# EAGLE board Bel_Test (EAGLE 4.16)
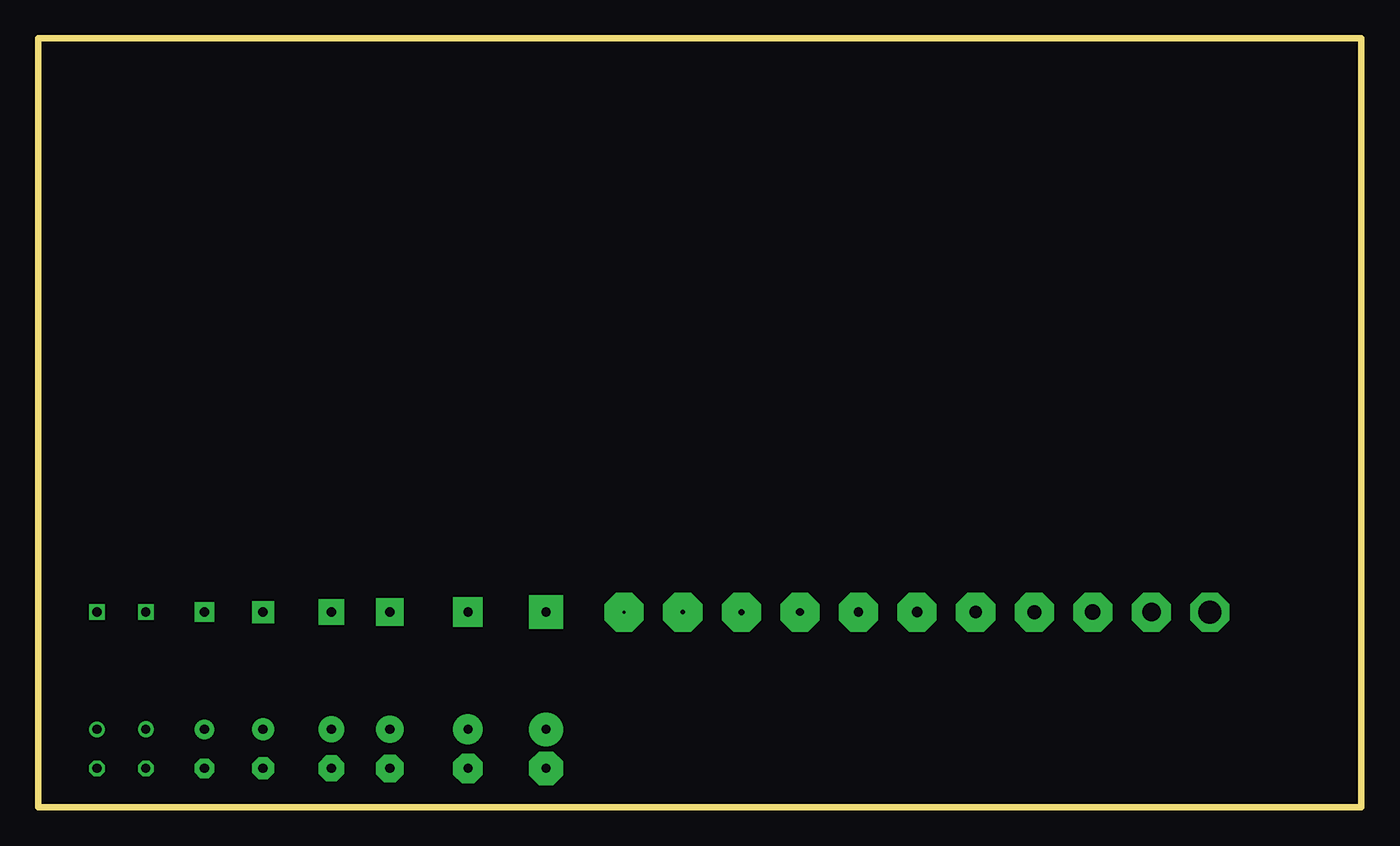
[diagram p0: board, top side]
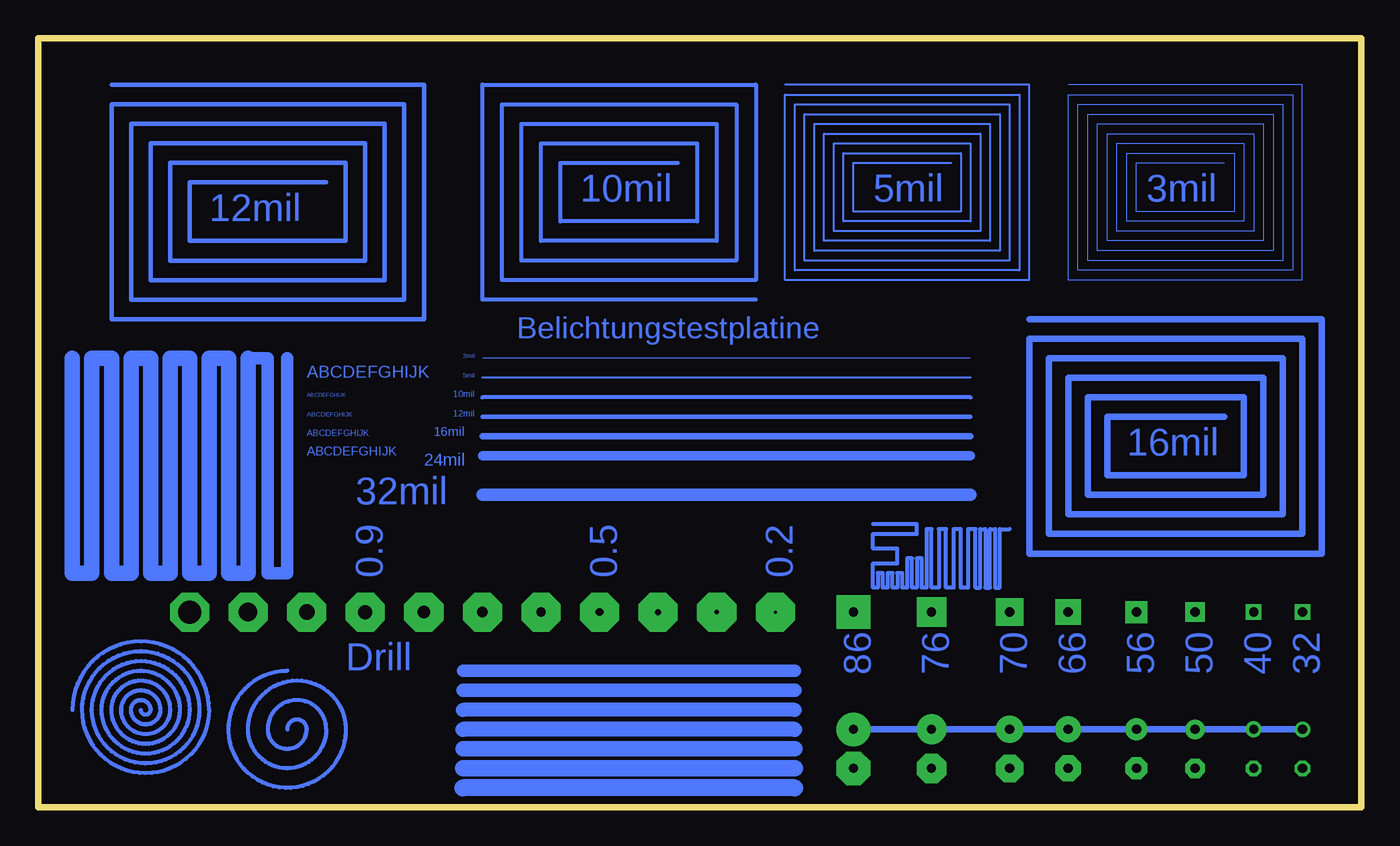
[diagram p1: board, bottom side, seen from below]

Size 86.03 x 50 mm. Coordinates in mm from the lower left corner, seen from the top.
Outline: 0,0 86.03,0 86.03,50 0,50 0,0
Copper layers (1*16): Top 0.035mm / dielectric 1.5mm / Bottom 0.035mm
Design rules "default": minimum track width 10mil, minimum drill 24mil, track to track 8mil, track to pad 8mil, pad to pad 8mil, via to via 8mil, smd to smd 8mil, copper to edge 40mil, drill to drill 8mil, minimum pad ring 10mil, minimum via ring 8mil, stop-mask expansion 4mil, vias tented up to drill 0mil, thermal gap 10mil

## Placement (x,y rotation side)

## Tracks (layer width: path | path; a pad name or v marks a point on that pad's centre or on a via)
S$1
  Bottom 0.254: 44.45,41.91 52.07,41.91 52.07,38.1 43.18,38.1 43.18,43.18 53.34,43.18 53.34,36.83 41.91,36.83 41.91,44.45 54.61,44.45 54.61,35.56 40.64,35.56 40.64,45.72 55.88,45.72 55.88,34.29 39.37,34.29 39.37,46.99 57.15,46.99 57.15,33.02 39.37,33.02
S$2
  Bottom 0.305: 67.31,40.64 76.2,40.64 76.2,36.83 66.04,36.83 66.04,41.91 77.47,41.91 77.47,35.56 64.77,35.56 64.77,43.18 78.74,43.18 78.74,34.29 63.5,34.29 63.5,44.45 80.01,44.45 80.01,33.02 62.23,33.02 62.23,45.72 81.28,45.72 81.28,31.75 60.96,31.75 60.96,46.99 81.28,46.99
S$3
  Bottom 0.127: 26.67,41.91 33.02,41.91 33.02,38.73 26.04,38.73 26.04,42.55 33.66,42.55 33.66,38.1 25.4,38.1 25.4,43.18 34.29,43.18 34.29,37.47 24.77,37.47 24.77,43.81 34.92,43.81 34.92,36.83 24.13,36.83 24.13,44.45 35.56,44.45 35.56,36.2 23.5,36.2 23.5,45.09 36.2,45.09 36.2,35.56 22.86,35.56 22.86,45.72 36.83,45.72 36.83,34.92 22.23,34.92 22.23,46.35 37.47,46.35 37.47,34.29 21.59,34.29 21.59,46.99 37.47,46.99
S$4
  Bottom 0.406: 8.89,25.4 16.51,25.4 16.51,21.59 7.62,21.59 7.62,26.67 17.78,26.67 17.78,20.32 6.35,20.32 6.35,27.94 19.05,27.94 19.05,19.05 5.08,19.05 5.08,29.21 20.32,29.21 20.32,17.78 3.81,17.78 3.81,30.48 21.59,30.48 21.59,16.51 2.54,16.51 2.54,31.75 21.59,31.75
S$5
  Bottom 0.076: 8.89,41.91 14.61,41.91 14.61,38.73 8.26,38.73 8.26,42.55 15.24,42.55 15.24,38.1 7.62,38.1 7.62,43.18 15.88,43.18 15.88,37.47 6.99,37.47 6.99,43.81 16.51,43.81 16.51,36.83 6.35,36.83 6.35,44.45 17.14,44.45 17.14,36.2 5.71,36.2 5.71,45.09 17.78,45.09 17.78,35.56 5.08,35.56 5.08,45.72 18.41,45.72 18.41,34.92 4.45,34.92 4.45,46.35 19.05,46.35 19.05,34.29 3.81,34.29 3.81,46.99 19.05,46.99
S$6
  Bottom 0.076: 25.4,29.21 57.15,29.21
S$7
  Bottom 0.127: 25.4,27.94 57.15,27.94
S$8
  Bottom 0.254: 25.4,26.67 57.15,26.67
S$9
  Bottom 0.305: 25.4,25.4 57.15,25.4
S$10
  Bottom 0.406: 25.4,24.13 57.15,24.13
S$11
  Bottom 0.61: 25.4,22.86 57.15,22.86
S$12
  Bottom 0.813: 25.4,20.32 57.15,20.32
S$13  (via drill 0.6 pad 0.81)
  other vias: 3.81,12.7
S$14  (via drill 0.6 pad 1.02)
  other vias: 6.99,12.7
S$15  (via drill 0.6 pad 1.27)
  other vias: 10.79,12.7
S$16  (via drill 0.6 pad 1.42)
  other vias: 14.61,12.7
S$17  (via drill 0.6 pad 1.68)
  other vias: 19.05,12.7
S$18  (via drill 0.6 pad 1.78)
  other vias: 22.86,12.7
S$19  (via drill 0.6 pad 1.93)
  other vias: 27.94,12.7
S$20  (via drill 0.6 pad 2.18)
  other vias: 33.02,12.7
S$28  (via drill 0.6 pad 0.81, 0.6 pad 1.02, 0.6 pad 1.27, 0.6 pad 1.42, 0.6 pad 1.68, 0.6 pad 1.78, 0.6 pad 1.93, 0.6 pad 2.18)
  Bottom 0.406: v3.81,5.08 v6.99,5.08 v10.79,5.08 v14.61,5.08 v19.05,5.08 v22.86,5.08 v27.94,5.08 v33.02,5.08
S$29  (via drill 0.6 pad 0.81)
  other vias: 3.81,2.54
S$30  (via drill 0.6 pad 1.02)
  other vias: 6.99,2.54
S$31  (via drill 0.6 pad 1.27)
  other vias: 10.79,2.54
S$32  (via drill 0.6 pad 1.42)
  other vias: 14.61,2.54
S$33  (via drill 0.6 pad 1.68)
  other vias: 19.05,2.54
S$34  (via drill 0.6 pad 1.78)
  other vias: 22.86,2.54
S$35  (via drill 0.6 pad 1.93)
  other vias: 27.94,2.54
S$36  (via drill 0.6 pad 2.18)
  other vias: 33.02,2.54
S$37  (via drill 0.5 pad 2.54)
  other vias: 49.53,12.7
S$38  (via drill 0.6 pad 2.54)
  other vias: 53.34,12.7
S$39  (via drill 0.7 pad 2.54)
  other vias: 57.15,12.7
S$40  (via drill 0.8 pad 2.54)
  other vias: 60.96,12.7
S$41  (via drill 0.9 pad 2.54)
  other vias: 64.77,12.7
S$42  (via drill 1 pad 2.54)
  other vias: 68.58,12.7
S$43  (via drill 1.2 pad 2.54)
  other vias: 72.39,12.7
S$44  (via drill 1.5 pad 2.54)
  other vias: 76.2,12.7
S$45  (via drill 0.2 pad 2.54)
  other vias: 38.1,12.7
S$46  (via drill 0.3 pad 2.54)
  other vias: 41.91,12.7
S$47  (via drill 0.4 pad 2.54)
  other vias: 45.72,12.7
S$48
  Bottom 0.813: 69.85,29.21 69.85,15.24 71.12,15.24 71.12,29.21 72.39,29.21
  Bottom 1.016: 72.39,29.21 72.39,15.24 73.66,15.24 73.66,29.21 74.93,29.21 74.93,15.24 76.2,15.24 76.2,29.21 77.47,29.21 77.47,15.24 78.74,15.24 78.74,29.21 80.01,29.21 80.01,15.24 81.28,15.24 81.28,29.21 82.55,29.21 82.55,15.24 83.82,15.24 83.82,29.21
S$49
  Bottom 0.813: 36.83,8.89 58.42,8.89
S$50
  Bottom 0.864: 36.83,7.62 58.42,7.62
S$51
  Bottom 0.914: 36.83,6.35 58.42,6.35
S$52
  Bottom 0.965: 36.83,5.08 58.42,5.08
S$53
  Bottom 1.016: 36.83,3.81 58.42,3.81
S$54
  Bottom 1.067: 36.83,2.54 58.42,2.54
S$55
  Bottom 1.118: 36.83,1.27 58.42,1.27
S$56
  Bottom 0.254: 69.85,8.89 arc-270 66.04,5.08 arc-180 72.39,5.08 arc-180 67.31,5.08 arc-180 71.12,5.08 arc-180 68.58,5.08 arc-180 69.85,5.08
S$57
  Bottom 0.254: 79.38,6.35 arc-180 78.74,6.35 arc-180 80.01,6.35 arc-180 78.11,6.35 arc-180 80.64,6.35 arc-180 77.47,6.35 arc-180 81.28,6.35 arc-180 76.83,6.35 arc-180 81.92,6.35 arc-180 76.2,6.35 arc-180 82.55,6.35 arc-180 75.56,6.35 arc-180 83.19,6.35 arc-180 74.93,6.35 arc-180 83.82,6.35
S$58
  Bottom 0.254: 22.86,18.1 23.5,18.1 23.5,14.29 23.81,14.29 23.81,18.1 24.13,18.1 24.13,14.29 24.45,14.29 24.45,18.1 24.77,18.1 24.77,14.29 25.08,14.29 25.08,18.1 25.56,18.1 25.56,14.29 26.04,14.29 26.04,18.1 26.51,18.1 26.51,14.29 26.99,14.29 26.99,18.1 27.46,18.1 27.46,14.29 27.94,14.29 27.94,18.1 28.26,18.1 28.26,14.29 28.57,14.29 28.57,16.19 28.89,16.19 28.89,14.29 29.21,14.29 29.21,16.19 29.53,16.19 29.53,14.29 29.84,14.29 29.84,15.24 30.16,15.24 30.16,14.29 30.48,14.29 30.48,15.24 30.8,15.24 30.8,14.29 31.11,14.29 31.11,15.24 31.43,15.24 31.43,14.29 31.75,14.29 31.75,15.88 30.16,15.88 30.16,16.83 31.75,16.83 31.75,17.78 28.89,17.78 28.89,18.41 31.75,18.41

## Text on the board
Bottom: 3mil | 5mil | 10mil | 12mil | Belichtungstestplatine | 3mil | 5mil | ABCDEFGHIJK | 10mil | ABCDEFGHIJK | 12mil | ABCDEFGHIJK | 16mil | ABCDEFGHIJK | 16mil | ABCDEFGHIJK | 24mil | 32mil | 0.2 | 0.5 | 0.9 | 32 | 40 | 50 | 56 | 66 | 70 | 76 | 86 | Drill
